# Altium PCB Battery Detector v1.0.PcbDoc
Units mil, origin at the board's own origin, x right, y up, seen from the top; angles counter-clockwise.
Board outline 2952.75 x 1181.14 mil, 2 copper layers (Top, Bottom); 48 components, 18 nets, 99 pads, 72 vias.
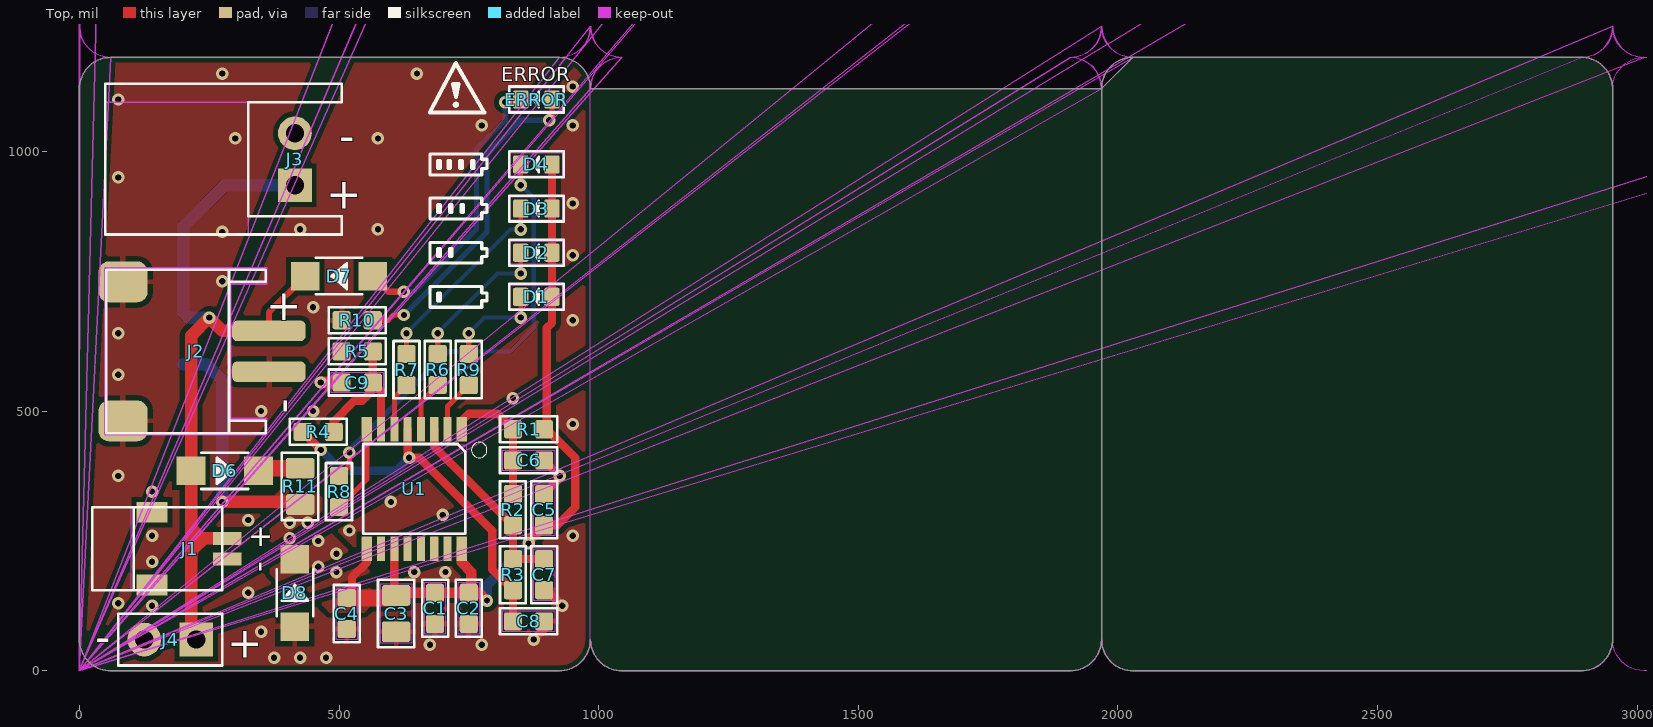
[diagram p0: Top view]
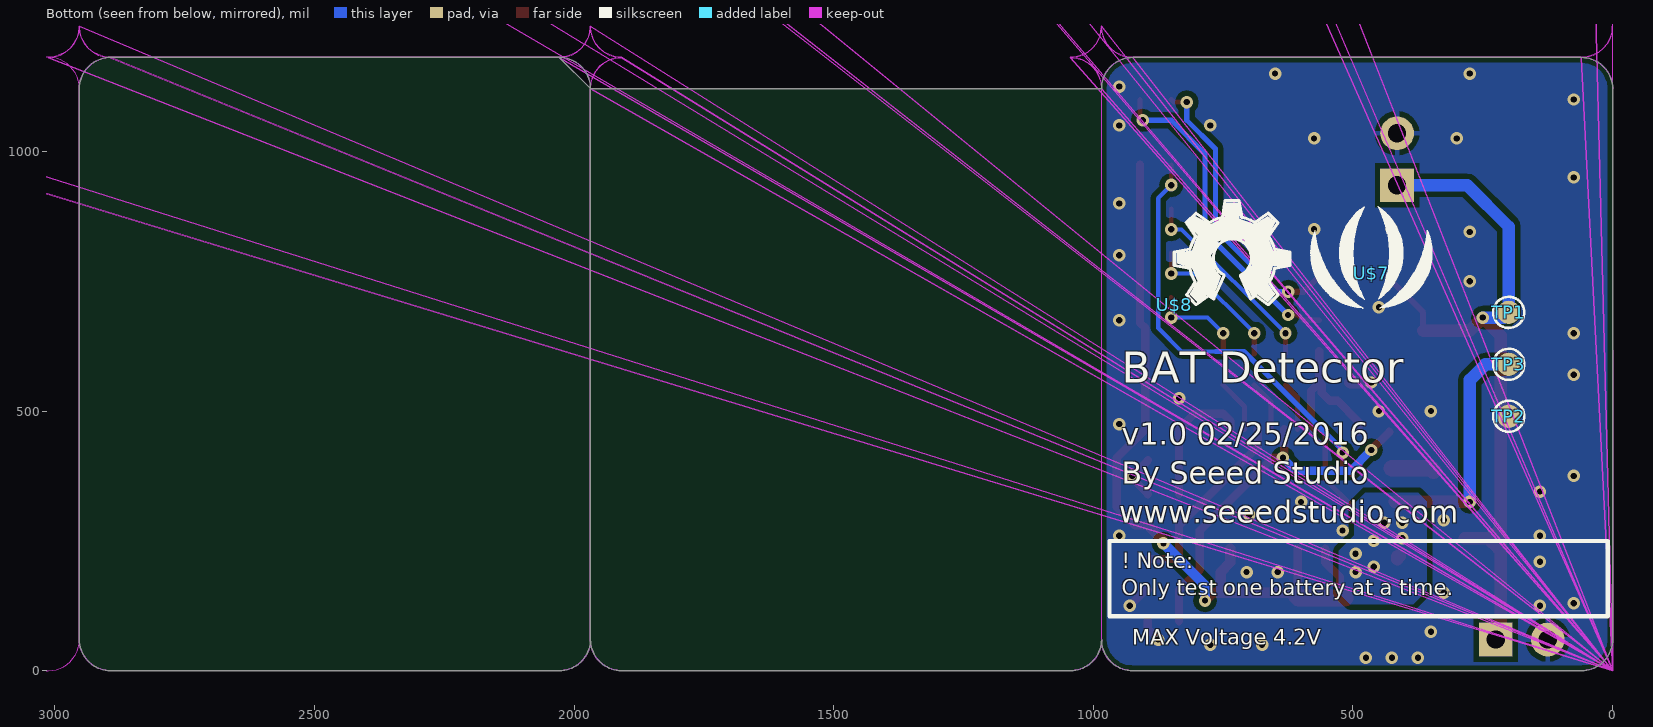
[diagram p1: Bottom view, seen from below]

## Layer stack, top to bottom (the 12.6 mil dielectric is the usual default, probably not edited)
Top Solder: solder mask 0.4, Solder Resist, Dk 3.5
Top: signal copper 1.378
Dielectric 1: dielectric 12.6, FR-4, Dk 4.8
Bottom: signal copper 1.378
Bottom Solder: solder mask 0.4, Solder Resist, Dk 3.5

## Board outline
1968.5,1121.14 cw(c2028.5,1121.14) 2028.5,1181.14 2892.75,1181.14 cw(c2892.75,1121.14) 2952.75,1121.14 2952.75,60.04 cw(c2892.75,60.04) 2892.75,0.04 2028.5,0.04 cw(c2028.5,60.04) 1968.5,60.04 1968.5,1121.14 1968.5,60 cw(c1908.5,60) 1908.5,0 1044.25,0 cw(c1044.25,60) 984.25,60 cw(c924.25,60) 924.25,0 60,0 cw(c60,60) 0,60 0,1121.1 cw(c60,1121.1) 60,1181.1 924.25,1181.1 cw(c924.25,1121.1) 984.25,1121.1 1968.5,1121.14 cw(c2028.5,1121.14)
cut-out: 60.24,1180.77 0,0 60.21,1180.77
cut-out: 936.25,2361.29 947.56,2357.86 957.99,2352.29 967.12,2344.79 974.62,2335.66 980.19,2325.23 983.62,2313.92 984.78,2302.16 0,0 984.28,2302.16 983.13,2313.82 979.73,2325.04 974.2,2335.38 966.77,2344.44 957.71,2351.87 947.37,2357.4 936.15,2360.8 924.49,2361.95 0,0 924.49,2362.45
cut-out: 1044.49,1180.77 0,0 1044.08,1180.81
cut-out: 2954.35,2313.86 2953.2,2302.2 0,0 2952.7,2302.2 2953.86,2313.96 2954.52,2316.15 2955.21,2316.69
cut-out: 2028.74,1180.81 0,0 2028,1180.88
cut-out: 3937.01,1240.94 0,0 3937.03,1241.1
cut-out: 3936.37,1229.34 3932.94,1218.03 3927.37,1207.6 3919.87,1198.47 3910.74,1190.97 3900.31,1185.4 3889,1181.97 3877.24,1180.81 0,0 3877.24,1181.31 3888.9,1182.46 3900.12,1185.86 3910.46,1191.39 3919.52,1198.82 3926.95,1207.88 3932.48,1218.22 3935.88,1229.44 3937.01,1240.94 3937.53,1241.1
cut-out: 3877.24,2361.99 1980.27,1206.37 1986.46,1198.82 1995.52,1191.39 2005.86,1185.86 2017.08,1182.46 2021.41,1182.03 3937.03,2302.2 3935.88,2313.86 3932.48,2325.08 3926.95,2335.42 3919.52,2344.48 3910.46,2351.91 3900.12,2357.44 3888.9,2360.84
cut-out: 60.23,2361.95 60.24,2361.95 30.34,1189.58 37.36,1185.82 48.58,1182.42 60.24,1181.27 60.21,1180.77 48.48,1181.93 37.17,1185.36 30.33,1189.02 0,0 30.32,1189.02 26.74,1190.93 17.61,1198.43 10.11,1207.56 4.54,1217.99 1.11,1229.3 0.45,1235.98 0.45,1241.06 1.6,1229.4 5,1218.18 10.53,1207.84 17.96,1198.78 27.02,1191.35 30.33,1189.58 60.23,2361.95 48.58,2360.8 37.36,2357.4 27.02,2351.87 17.96,2344.44 10.53,2335.38 5,2325.04 1.6,2313.82 0.45,2302.16 0.24,1238.08 0.45,1235.98 0,0 -0.05,1241.06 -0.03,1240.82 -0.05,2302.16 1.11,2313.92 4.54,2325.23 10.11,2335.66 17.61,2344.79 26.74,2352.29 37.17,2357.86 48.48,2361.29 60.24,2362.45
cut-out: 3889,2361.33 3900.31,2357.9 3910.74,2352.33 3919.87,2344.83 3927.37,2335.7 3932.94,2325.27 3936.37,2313.96 3937.53,2302.2 2021.63,1182.01 2028.74,1181.31 2028,1180.88 2020.9,1181.58 0,0 2020.68,1181.6 2016.98,1181.97 2005.67,1185.4 1995.24,1190.97 1986.11,1198.47 1979.84,1206.11 0,0 1979.7,1206.28 1978.61,1207.6 1973.04,1218.03 1969.61,1229.34 1968.74,1238.13 1967.87,1229.3 1964.44,1217.99 1958.87,1207.56 1951.37,1198.43 1942.24,1190.93 1931.81,1185.36 1920.5,1181.93 1908.74,1180.77 0,0 1908.74,1181.27 1920.4,1182.42 1931.62,1185.82 1941.96,1191.35 1951.02,1198.78 1958.45,1207.84 1963.98,1218.18 1967.38,1229.4 1968.49,1240.68 1968.49,1240.72 0,0 1968.45,1241.1 1968.46,1241.02 1968.53,1241.06 1968.5,1240.82 1968.95,1241.1 1968.96,1241.02 1969.03,1241.06 1968.99,1240.68 1970.1,1229.44 1973.5,1218.22 1979.03,1207.88 1980.13,1206.54 3877.24,2362.49
cut-out: 984.74,1240.66 985.85,1229.4 989.25,1218.18 994.78,1207.84 1002.21,1198.78 1011.27,1191.35 1021.61,1185.82 1032.83,1182.42 1044.49,1181.27 1044.08,1180.81 1032.73,1181.93 1021.42,1185.36 1010.99,1190.93 1001.86,1198.43 994.36,1207.56 988.79,1217.99 985.36,1229.3 984.49,1238.11 983.62,1229.3 980.19,1217.99 974.62,1207.56 967.12,1198.43 957.99,1190.93 947.56,1185.36 938.37,1182.57 0,0 937.64,1182.35 936.25,1181.93 924.49,1180.77 0,0 924.49,1181.27 936.15,1182.42 938.19,1183.04 984.2,1241.06 984.21,1240.97 984.28,1241.06 984.24,1240.66 984.26,1240.5 984.22,1240.45 984.21,1240.34 938.91,1183.26 938.82,1183.23 938.27,1182.54 938.37,1182.57 938.91,1183.26 947.37,1185.82 957.71,1191.35 966.77,1198.78 974.2,1207.84 979.73,1218.18 983.13,1229.4 984.21,1240.34 984.26,1240.41 984.26,1240.5 984.7,1241.06 984.71,1240.97 984.78,1241.06
cut-out: 2953.24,1240.7 2954.35,1229.44 2957.75,1218.22 2963.28,1207.88 2970.71,1198.82 2979.77,1191.39 2990.11,1185.86 3001.33,1182.46 3012.99,1181.31 3011.97,1180.91 3012.99,1180.81 0,0 3011.97,1180.91 3001.23,1181.97 2989.92,1185.4 2979.49,1190.97 2970.36,1198.47 2962.86,1207.6 2957.29,1218.03 2953.86,1229.34 2952.99,1238.15 2952.12,1229.34 2948.69,1218.03 2943.12,1207.6 2935.62,1198.47 2926.49,1190.97 2916.06,1185.4 2904.75,1181.97 2892.99,1180.81 0,0 2892.99,1181.31 2904.65,1182.46 2915.87,1185.86 2926.21,1191.39 2935.27,1198.82 2942.7,1207.88 2948.23,1218.22 2951.63,1229.44 2952.74,1240.7 2952.72,1240.87 0,0 2952.7,1241.1 2952.7,1241.07 2952.78,1241.1 2952.76,1240.91 2953.2,1241.1 2953.21,1241.07 2953.28,1241.1
cut-out: 3012.26,2361.92 3012.99,2361.99 2955.21,2316.69 2955.4,2317.34 2954.72,2316.8 2954.52,2316.15 0,0 2954.72,2316.8 2957.29,2325.27 2962.86,2335.7 2970.36,2344.83 2979.49,2352.33 2989.92,2357.9 3001.23,2361.33 3012.99,2362.49
cut-out: 3012.26,2361.92 3001.33,2360.84 2990.11,2357.44 2979.77,2351.91 2970.71,2344.48 2963.28,2335.42 2957.75,2325.08 2955.4,2317.34
cut-out: 3997.28,2362.28 4861.53,2362.28 cw(c4861.53,2302.28) 4921.53,2302.28 4921.53,1241.18 cw(c4861.53,1241.18) 4861.53,1181.18 3997.28,1181.18 cw(c3997.28,1241.18) 3937.28,1241.18 3937.28,2302.28 cw(c3997.28,2302.28)
cut-out: 3997.05,1181.22 4861.3,1181.22 cw(c4861.3,1121.22) 4921.3,1121.22 4921.3,60.12 cw(c4861.3,60.12) 4861.3,0.12 3997.05,0.12 cw(c3997.05,60.12) 3937.05,60.12 3937.05,1121.22 cw(c3997.05,1121.22)
cut-out: 3012.76,1181.14 3877.01,1181.14 cw(c3877.01,1121.14) 3937.01,1121.14 3937.01,60.04 cw(c3877.01,60.04) 3877.01,0.04 3012.76,0.04 cw(c3012.76,60.04) 2952.76,60.04 2952.76,1121.14 cw(c3012.76,1121.14)
cut-out: 1043.76,1180.84 1032.59,1179.74 1021.37,1176.34 1011.03,1170.81 1001.97,1163.38 994.54,1154.32 989.01,1143.98 985.61,1132.76 984.46,1121.1 0,0 983.96,1121.1 985.12,1132.86 988.55,1144.17 994.12,1154.6 1001.62,1163.73 1010.75,1171.23 1021.18,1176.8 1032.49,1180.23 1044.25,1181.39
cut-out: 0,0 1043.76,1180.84 1044.25,1180.89
cut-out: 1920.26,1180.23 1931.57,1176.8 1942,1171.23 1951.13,1163.73 1958.63,1154.6 1964.2,1144.17 1967.63,1132.86 1968.79,1121.1 0,0 1968.29,1121.1 1967.14,1132.76 1963.74,1143.98 1958.21,1154.32 1950.78,1163.38 1941.72,1170.81 1931.38,1176.34 1920.16,1179.74 1908.5,1180.89 0,0 1908.5,1181.39
cut-out: 1044.26,2361.93 1032.83,2360.8 1021.61,2357.4 1011.27,2351.87 1002.21,2344.44 994.78,2335.38 989.25,2325.04 985.85,2313.82 984.7,2302.16 0,0 984.2,2302.16 985.36,2313.92 988.79,2325.23 994.36,2335.66 1001.86,2344.79 1010.99,2352.29 1021.42,2357.86 1032.73,2361.29 1044.49,2362.45
cut-out: 0,0 1044.26,2361.93 1044.49,2361.95
cut-out: 1920.5,2361.29 1931.81,2357.86 1942.24,2352.29 1951.37,2344.79 1958.87,2335.66 1964.44,2325.23 1967.87,2313.92 1969.03,2302.16 0,0 1968.53,2302.16 1967.38,2313.82 1963.98,2325.04 1958.45,2335.38 1951.02,2344.44 1941.96,2351.87 1931.62,2357.4 1920.4,2360.8 1908.74,2361.95 0,0 1908.74,2362.45
cut-out: 2028.27,2361.94 2017.08,2360.84 2005.86,2357.44 1995.52,2351.91 1986.46,2344.48 1979.03,2335.42 1973.5,2325.08 1970.1,2313.86 1968.95,2302.2 0,0 1968.45,2302.2 1969.61,2313.96 1973.04,2325.27 1978.61,2335.7 1986.11,2344.83 1995.24,2352.33 2005.67,2357.9 2016.98,2361.33 2028.74,2362.49
cut-out: 0,0 2028.27,2361.94 2028.74,2361.99
cut-out: 2904.75,2361.33 2916.06,2357.9 2926.49,2352.33 2935.62,2344.83 2943.12,2335.7 2948.69,2325.27 2952.12,2313.96 2953.28,2302.2 0,0 2952.78,2302.2 2951.63,2313.86 2948.23,2325.08 2942.7,2335.42 2935.27,2344.48 2926.21,2351.91 2915.87,2357.44 2904.65,2360.84 2892.99,2361.99 0,0 2892.99,2362.49
cut-out: 4850,-189.37 ccw(c4850,-150) 4889.37,-150 ccw(c4850,-150) 4850,-110.63 ccw(c4850,-150) 4810.63,-150 ccw(c4850,-150)
cut-out: 4850,2460.63 ccw(c4850,2500) 4889.37,2500 ccw(c4850,2500) 4850,2539.37 ccw(c4850,2500) 4810.63,2500 ccw(c4850,2500)
cut-out: 75,2460.63 ccw(c75,2500) 114.37,2500 ccw(c75,2500) 75,2539.37 ccw(c75,2500) 35.63,2500 ccw(c75,2500)
cut-out: 75,-189.37 ccw(c75,-150) 114.37,-150 ccw(c75,-150) 75,-110.63 ccw(c75,-150) 35.63,-150 ccw(c75,-150)

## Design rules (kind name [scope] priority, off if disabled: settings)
BoardOutlineClearance mdCopperDimension [All] p1: gap=10 ignorepadtopadclearanceinfootprint=FALSE except(0: Arc-SplitContinuation Track-SplitContinuation SMDPad-SplitContinuation THPad-SplitContinuation Via-SplitContinuation Fill-SplitContinuation Poly-SplitContinuation Region-SplitContinuation Text-SplitContinuation)
Clearance Clearance_for_PolygonClass_Isolate_10 [InPolygonClass('Isolate_10') vs IsArc Or IsTrack Or IsPad Or IsVia Or IsFill Or IsRegion Or IsText] p1: gap=10 ignorepadtopadclearanceinfootprint=FALSE
Clearance "Clearance (Same Net)" [All] p2: gap=6 ignorepadtopadclearanceinfootprint=FALSE
Clearance [All] p3: gap=6 ignorepadtopadclearanceinfootprint=FALSE
HoleSize [All] p1: absolutevalues=TRUE maxlimit=100000 minlimit=12 maxpercent=80.000 minpercent=20.000
HoleToHoleClearance mdDrill [All] p1: gap=10 allowstackedmicrovias=TRUE
MinimumSolderMaskSliver [All] p1 off: minsoldermaskwidth=10
PasteMaskExpansion Expansion_SMDPaste_OFF [InPadClass('SMDPaste_OFF')] p1: expansion=0
PasteMaskExpansion mlMinCreamFrame [All] p2: expansion=0
PolygonConnect PolygonConnect_For_PolygonThermal_ON_Width100000_Gap100000 [InPolygonClass('PolygonThermal_ON_Width100000_Gap100000') vs Not IsVia] p1: connectstyle=Relief reliefconductorwidth=10 reliefentries=4 polygonreliefangle="90 Angle" airgapwidth=10
PolygonConnect PolygonConnect_For_PolygonThermal_ON_Width50000_Gap100000 [InPolygonClass('PolygonThermal_ON_Width50000_Gap100000') vs Not IsVia] p2: connectstyle=Relief reliefconductorwidth=5 reliefentries=4 polygonreliefangle="90 Angle" airgapwidth=10
PolygonConnect PolygonConnect_For_PolygonThermal_OFF [InPolygonClass('PolygonThermal_OFF')] p3: connectstyle=Direct reliefconductorwidth=10 reliefentries=4 polygonreliefangle="90 Angle" airgapwidth=10
PolygonConnect ThermalVias [IsVia] p4: connectstyle=Direct reliefconductorwidth=10 reliefentries=4 polygonreliefangle="90 Angle" airgapwidth=10
PolygonConnect [All] p5: connectstyle=Relief reliefconductorwidth=10 reliefentries=4 polygonreliefangle="90 Angle" airgapwidth=10
RoutingVias [All] p1: holewidth=12 width=24 viastyle="Through Hole" minholewidth=12 minwidth=24 maxholewidth=100 maxwidth=100
SolderMaskExpansion Expansion_SMDSolder_OFF [InPadClass('SMDSolder_OFF')] p1: expansion=0
SolderMaskExpansion mlMinStopFrame [All] p2: expansion=2
Width [All] p1: maxlimit=10000 minlimit=5 preferedwidth=5
26 further rules are at their usual default settings.

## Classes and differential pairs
polygon class PolygonThermal_ON_Width100000_Gap100000: Polygon_1_Net_GND Polygon_2_Net_GND
polygon class PolygonThermal_ON_Width50000_Gap100000: Polygon_2_Net_VCC
polygon class PolygonThermal_OFF: Polygon_1_Net_VCC
polygon class Isolate_10: Polygon_1_Net_GND Polygon_1_Net_VCC Polygon_2_Net_GND Polygon_2_Net_VCC
pad class SMDSolder_OFF: P1-P$1 P2-P$1 P3-P$1 P4-P$1 P5-P$1 P6-P$1 P7-P$1 P8-P$1
pad class SMDPaste_OFF: P1-P$1 P2-P$1 P3-P$1 P4-P$1 P5-P$1 P6-P$1 P7-P$1 P8-P$1 TP1-T TP2-T TP3-T

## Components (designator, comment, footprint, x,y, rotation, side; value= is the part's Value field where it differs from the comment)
C1 "DNP" C0603 685,120 r180 top
C2 "100nF" C0603 750,120 r180 top
C3 "10uF" C0805 610,110 r0 top
C4 "100nF" C0603 515,110 r180 top
C5 "DNP" C0603 895,310 r0 top
C6 "DNP" C0603 865,405 r270 top
C7 "DNP" C0603 895,185 r180 top
C8 "DNP" C0603 865,95 r270 top
C9 "DNP" C0603 535,555 r90 top
D1 "Green" LED-0603 880,720 r180 top
D2 "Green" LED-0603 880,805 r180 top
D3 "Green" LED-0603 880,890 r180 top
D4 "Green" LED-0603 880,975 r180 top
D6 "B5819W" SOD-123 280,385 r0 top
D7 "B5819W" SOD-123 500,760 r180 top
D8 "MMSZ4689" SOD-123 415,150 r90 top
ERROR "RED" LED-0603 880,1100 r180 top
FR1 "" SEEEDSTUDIO-PCB-FRAME 105,-2205 r0 top
FR2 "" SEEEDSTUDIO-PCB-FRAME 235,-1840 r0 top
J1 "JST-2P-SMD'1.0" HW2-SMD-1.0-90D 275,235 r0 top
J2 "JST-2P-SMD'2.0" HW2-SMD-2.0-90D 170,615 r270 top
J3 "JST-2P-DIP'2.54/90D'" JST2-2.54-90D 325,985 r0 top
J4 "DNP" H2-2.54 175,60 r270 top
P1 "" ROUND-MARK-1.0 400,2500 r270 bottom
P2 "" ROUND-MARK-1.0 400,2500 r90 top
P3 "" ROUND-MARK-1.0 275,-150 r270 bottom
P4 "" ROUND-MARK-1.0 275,-150 r90 top
P5 "" ROUND-MARK-1.0 4650,-150 r270 bottom
P6 "" ROUND-MARK-1.0 4650,-150 r90 top
P7 "" ROUND-MARK-1.0 4650,2500 r270 bottom
P8 "" ROUND-MARK-1.0 4650,2500 r90 top
R1 "430k" R0603 865,465 r90 top
R2 "22k" R0603 835,310 r180 top
R3 "15k" R0603 835,185 r180 top
R4 "18k" R0603 460,460 r270 top
R5 "270k" R0603 535,615 r90 top
R6 "510R" R0603 690,580 r180 top
R7 "510R" R0603 630,580 r180 top
R8 "510R" R0603 500,345 r180 top
R9 "510R" R0603 750,580 r180 top
R10 "1k" R0603 535,675 r270 top
R11 "22R" R0805 425,355 r180 top
TP1 "" TP-D45MIL 200,690 r180 bottom
TP2 "" TP-D45MIL 200,490 r180 bottom
TP3 "" TP-D45MIL 200,590 r180 bottom
U1 "CN1185" TSSOP16-0.65-5X4.4MM 645,350 r180 top
U$7 "" SEEED-SILK-280*268MIL 465,765 r180 bottom
U$8 "" OSHW_FILLX200_NOTEXT 844.25,705 r180 bottom

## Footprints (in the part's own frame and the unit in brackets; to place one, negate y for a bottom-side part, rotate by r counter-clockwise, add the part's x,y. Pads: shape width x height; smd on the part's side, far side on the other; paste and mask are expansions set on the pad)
C0603 [mil] "C0603"
  rrect25% 35x35 smd: 1(0,30) 2(0,-30)
  Top keep-out region: -20,50 20,50 20,-50 -20,-50
  silkscreen extent -25,-55 25,55
C0805 [mil] "C0805"
  rrect25% 55x40 smd: 1(0,35) 2(0,-35)
  Top keep-out region: -30,57.5 30,57.5 30,-57.5 -30,-57.5
  silkscreen extent -35,-65 35,65
H2-2.54 [mil] "H2-2.54"
  rect 65x65 / inner rect 60x60 / far side rect 65x65 hole 35: 1(0,50)
  round 65 / inner round 60 / far side round 65 hole 35: 2(0,-50)
  Top keep-out region: -50,-100 -50,100 50,100 50,-100
  Top keep-out lines w0: 50,-100 50,100 -50,100 -50,-100
  silkscreen extent -50,-100 50,100
HW2-SMD-1.0-90D [mil] "HW2-SMD-1.0-90D"
  rect 60x40 smd: 3(-135,70) 4(-135,-70)
  rect 55x25 smd: +(10,20) -(10,-20)
  Top keep-out region: -175,-80 -175,80 0,80 0,-80
  silkscreen extent -250,-80 0,80
HW2-SMD-2.0-90D [mm] "HW2-SMD-2.0-90D"
  rrect50% 2x2.4 smd: 3(3.4,-2.181) 4(-3.4,-2.181)
  rrect50% 1x3.6 smd: +(-1,4.953) -(1,4.953)
  Top keep-out lines w0.127: 4.064,-3.048 -4.064,-3.048 -4.064,4.826 -3.302,4.826 -3.302,3.048 3.302,3.048 3.302,4.826 4.064,4.826 4.064,-3.048
  silkscreen extent -4,-3 4,4.8
JST2-2.54-90D [mil] "JST2-2.54-90D"
  rect 65x65 / inner rect 60x60 / far side rect 65x65 hole 35: +(90,-50)
  round 65 / inner round 60 / far side round 65 hole 35: -(90,50)
  Top keep-out region: 0,-145 0,-110 180,-110 180,-145
  Top keep-out region: -275,-145 -275,110 0,110 0,-145
  Top keep-out region: -275,110 -275,145 180,145 180,110
  silkscreen extent -275,-145 180,145
LED-0603 [mil] "LED-0603"
  rrect25% 30x35 smd: +(-30,0) -(30,0)
  Top keep-out region: -50,-22.5 -50,22.5 50,22.5 50,-22.5
  silkscreen extent -52,-25 52,25
OSHW_FILLX200_NOTEXT [mil] "OSHW_FILLX200_NOTEXT"
  silkscreen extent 0,0 223,200
R0603 [mil] "R0603"
  rrect25% 35x35 smd: 1(0,30) 2(0,-30)
  silkscreen extent -25,-55 25,55
R0805 [mil] "R0805"
  rrect25% 55x40 smd: 1(0,35) 2(0,-35)
  silkscreen extent -35,-65 35,65
ROUND-MARK-1.0 [mil] "ROUND-MARK-1.0"
  rrect100% 40x40 smd paste-20 mask-20: P$1(0,0)
  Top circle w8: c0,0 r40
SEEED-SILK-280*268MIL [mil] "SEEED-SILK-280*268MIL"
  silkscreen extent -118,-68 118,130
SEEEDSTUDIO-PCB-FRAME [mil] "SEEEDSTUDIO-PCB-FRAME"
SOD-123 [mil] "SOD-123"
  rect 55x55 smd: +(-65,0) -(65,0)
  silkscreen extent -45,-35 45,35
TP-D45MIL [mil] "TP-D45MIL"
  rrect100% 45x45 smd paste-22.5: T(0,0)
  silkscreen extent -30,-30 30,30
TSSOP16-0.65-5X4.4MM [mil] "TSSOP16-0.65-5X4.4MM"
  rect 19.69x47.24 smd: 1(-91.54,-115.16) 8(91.54,-115.16) 9(91.54,115.16) 16(-91.54,115.16)
  rect 15.75x47.24 smd: 2(-63.98,-115.16) 3(-38.39,-115.16) 4(-12.8,-115.16) 5(12.8,-115.16) 6(38.39,-115.16) 7(63.98,-115.16) 10(63.98,115.16) 11(38.39,115.16) 12(12.8,115.16) 13(-12.8,115.16) 14(-38.39,115.16) 15(-63.98,115.16)
  Top keep-out region: -100,-85 -100,85 100,85 100,-85
  silkscreen extent -140,-90 98,87

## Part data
C1 C2 C4 C5 C6 C7 C8 C9: library part C0603
C3: library part C0805
D1 D2 D3 D4 ERROR: library part LED-0603
D6 D7 D8: library part SOD-123
FR1 FR2: library part SEEEDSTUDIO-PCB-FRAME
J1: library part HW2-SMD-1.0-90D
J2: library part HW2-SMD-2.0-90D
J3: library part JST2-2.54-90D
J4: library part H2-2.54
P1 P2 P3 P4 P5 P6 P7 P8: library part ROUND-MARK-1.0
R1 R2 R3 R4 R5 R6 R7 R8 R9 R10: library part R0603
R11: library part R0805
TP1 TP2 TP3: library part TP-D45MIL
U1: library part TSSOP16-0.65-5X4.4MM
U$7: library part SEEED-SILK-280*268MIL
U$8: library part OSHW_FILLX200_NOTEXT

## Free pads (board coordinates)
  round 78.74 hole 78.74 unplated: MH1(75,-150) MH2(4850,-150) MH3(4850,2500) MH4(75,2500)

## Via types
v1: diameter 24/24 (per signal layer), hole 12, Top to Bottom, tented both sides, 68 vias
v2: diameter 25/25 (per signal layer), hole 12, Top to Bottom, tented both sides, 4 vias

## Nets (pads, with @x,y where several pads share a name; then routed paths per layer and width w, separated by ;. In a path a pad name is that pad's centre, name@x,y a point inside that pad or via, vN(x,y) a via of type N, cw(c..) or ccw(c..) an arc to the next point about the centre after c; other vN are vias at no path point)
GND: C1.1 C2.1 C3.2 C4.1 C5.1 C6.1 C7.1 C8.1 C9.1 D8.+ J1.3 J1.4 J1.- J2.3 J2.4 J2.- J3.- J4.2 R5.1 R10.2 TP2.T U1.12 U1.13 U1.14 | length 220.6
  Top w16: v1(875,60) 895,80 C8.1 ; C7.1 900,155 v1(930,125) ; C5.1 925,370 v1(925,375) C6.1
  Top w24: v1(465,555) C9.1
  other v1: 375,25 425,25 475,25 675,50 775,50 350,75 140,125 75,130 325,150 645,190 705,190 140,210 140,260 950,260 520,270 325,290 700,300 600,325 140,345 75,375 950,475 350,500 450,500 835,525 75,570 75,650 950,675 450,700 275,750 950,800 275,845 425,850 575,850 950,900 75,950 300,1025 575,1025 775,1050 950,1050 75,1100 950,1125 275,1150 650,1150
N$1: R7.1 U1.6 | length 94.5
  Top w10: U1.6 606.61,526.61 R7.1
N$2: D6.- R11.2 | length 82.1
  Top w32: D6.- 350,390 R11.2
N$3: C6.2 R1.1 R2.2 U1.1 | length 257.8
  Top w16: U1.1 736.54,481.54 750,495 805,495 R1.1 C6.2 R2.2
N$4: C7.2 R2.1 R3.2 U1.3 | length 373
  Top w16: U1.3 683.39,431.61 R2.1 R3.2 C7.2
N$5: C8.2 R3.1 R4.2 U1.5 | length 712.3
  Top w16: R4.2 v1(465,425) ; U1.5 632.2,412.8 v1(635,410) 655,410 795,270 795,195 R3.1 C8.2
  Bottom w16: v1(465,425) 505,385 610,385 v1(635,410)
N$6: R9.1 U1.2 | length 101.8
  Top w10: U1.2 708.98,508.98 R9.1
N$7: R6.1 U1.4 | length 98.2
  Top w10: U1.4 657.8,517.8 R6.1
N$8: R8.1 U1.8 | length 172.3
  Top w10: R8.1 553.46,368.46 U1.8
N$9: D6.+ D7.- J1.+ J2.+ J3.+ J4.1 TP1.T | length 1494.8
  Top w12: J2.+ 365,690 D7.-
  Top w24: 220,235 240,255 ; J4.1 215,70 215,250 ; J1.+ 240,255 ; J2.+ 275.63,654.37 v1(250,680) 215,645 D6.+ 215,275 ; 215,250 220,255 235,255 ; 215,250 215,275 ; 215,275 235,255 ; 235,255 240,255
  Bottom w24: v1(250,680) 210,680 TP1.T 200,855 280,935 J3.+
N$10: D1.- R9.2 | length 192.4
  Top w8: v2(850,680) D1.-
  Top w10: R9.2 v1(750,650)
  Bottom w8: v1(750,650) 780,680 v2(850,680)
N$11: C9.2 R4.1 R5.2 U1.7 | length 291.3
  Top w16: R4.1 490,480 530,520 545,520 560,535 560,550 C9.2 ; R5.2 C9.2 ; U1.7 581.02,538.98 C9.2
N$12: D2.- R6.2 | length 287.6
  Top w8: v2(850,765) D2.-
  Top w10: R6.2 v1(690,650)
  Bottom w8: v1(690,650) 805,765 v2(850,765)
N$14: D3.- R7.2 | length 382.8
  Top w8: v2(850,850) D3.-
  Top w10: R7.2 v1(630,650)
  Bottom w8: v1(630,650) 830,850 841.06,850 v2(850,850)
N$16: D4.- R8.2 | length 836
  Top w8: v2(850,935) D4.-
  Top w10: R8.2 520,395 v1(520,420)
  Bottom w8: 765,615 830,615 875,660 875,910 v2(850,935)
  Bottom w10: v1(520,420) 520,425 710,615 765,615
N$17: ERROR.+ R10.1 | length 629.4
  Top w10: R10.1 595,675 605,685 v1(625,685) ; v1(905,1060) 910,1065 ERROR.+
  Bottom w10: v1(625,685) 785,845 785,995 850,1060 v1(905,1060)
N$18: D7.+ ERROR.- | length 562
  Top w10: v1(820,1095) 845,1095 ERROR.-
  Top w12: D7.+ 595,730 v1(625,730)
  Bottom w10: v1(625,730) 645,730 765,850 765,1005 820,1060 v1(820,1095)
VCC: C1.2 C2.2 C3.1 C4.2 C5.2 D1.+ D2.+ D3.+ D4.+ D8.- R1.2 R11.1 TP3.T U1.9 U1.11 U1.16 | length 2003.4
  Top w16: C4.2@525,155 525,180 553.46,208.46 U1.9 ; U1.11 606.61,148.39 C3.1 ; C5.2 920,280 955,315 955,410 900,465 R1.2 900,470 900,660 910,670 D1.+ D2.+ D3.+ D4.+
  Top w20: C3.1 615,150 C1.2 C2.2 ; U1.16 736.54,208.46 755,190 755,155 C2.2 ; v1(785,135) 770,150 C2.2 ; v1(865,245) 865,250 C5.2
  Top w24: v1(275,325) R11.1@405,325 ; D8.-@410,220 D8.- D8.-@415,220 ; R11.1@410,320 R11.1@405,325 ; R11.1@420,325 R11.1@405,325
  Top w32: C4.2 605,140 C3.1
  Bottom w20: v1(785,135) 785,165 v1(865,245)
  Bottom w24: TP3.T 245,590 275,560 v1(275,325)
  other v1: 495,190 460,200 495,225 460,250 405,255 405,285 440,285
pads on no net: P1.P$1 P2.P$1 P3.P$1 P4.P$1 P5.P$1 P6.P$1 P7.P$1 P8.P$1 U1.10 U1.15

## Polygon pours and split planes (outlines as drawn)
GND on Top "Polygon_1_Net_GND" (solid, remove dead copper, pour order 3): 155,1220 1025,1220 1025,-35 -55,-35 -55,1225 155,1225
VCC on Top "Polygon_1_Net_VCC" (solid, remove dead copper, pour order 0): 386.69,348 453.31,348 460.66,340.66 468,333.31 468,300 468,283.31 523,228.31 523,208.31 523.31,208 543.31,208 563,188.31 563,126.69 548.31,112 481.69,112 431.69,162 391.69,162 367,186.69 367,328.31
GND on Bottom "Polygon_2_Net_GND" (solid, remove dead copper, pour order 2): 185,1235 1055,1235 1055,-20 -25,-20 -25,1240 185,1240
VCC on Bottom "Polygon_2_Net_VCC" (solid, remove dead copper, pour order 1): 395,342.5 476.04,342.5 497.5,321.04 497.5,261.04 527.5,231.04 527.5,148.96 506.04,127.5 383.96,127.5 357.5,153.96 357.5,326.04 373.96,342.5

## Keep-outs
Keep-Out Layer:
  the board outline again, w0

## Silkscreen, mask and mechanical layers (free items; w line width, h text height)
Top Overlay:
  circle w6: c725,1090 r3
  lines w6: 675,700 675,740 775,740 775,727.5 785,727.5 785,712.5 775,712.5 775,700 675,700 ; 675,785 675,825 775,825 775,812.5 785,812.5 785,797.5 775,797.5 775,785 675,785 ; 675,870 675,910 775,910 775,897.5 785,897.5 785,882.5 775,882.5 775,870 675,870 ; 675,955 675,995 775,995 775,985 785,985 785,967.5 775,967.5 775,955 675,955 ; 690,712.5 695,712.5 695,727.5 690,727.5 690,712.5 ; 690,797.5 695,797.5 695,812.5 690,812.5 690,797.5 ; 690,882.5 695,882.5 695,897.5 690,897.5 690,882.5 ; 690,967.5 695,967.5 695,982.5 690,982.5 690,967.5 ; 710,967.5 715,967.5 715,982.5 710,982.5 710,967.5 ; 712.5,797.5 717.5,797.5 717.5,812.5 712.5,812.5 712.5,797.5 ; 712.5,882.5 717.5,882.5 717.5,897.5 712.5,897.5 712.5,882.5 ; 732.5,967.5 737.5,967.5 737.5,982.5 732.5,982.5 732.5,967.5 ; 735,882.5 740,882.5 740,897.5 735,897.5 735,882.5 ; 755,967.5 760,967.5 760,982.5 755,982.5 755,967.5
  lines w8: 725,1105 720,1130 725,1130 ; 725,1105 730,1130 725,1130 ; 725,1105 725,1130 ; 675,1075 780,1075 725,1170 675,1075
  text "ERROR" at 812.5,1135 h27.2
  text "-" at 500.35,1000.52 h59.5
  text "+" at 475,890 h59.5
  text "+" at 360,675 h59.5
  text "-" at 420,495 h59.5 r90
  text "+" at 325,240 h42.5
  text "-" at 365,190 h42.5 r90
  text "-" at 30.35,35.52 h59.5
  text "+" at 285,25 h59.5
Bottom Overlay:
  lines w8: 9.25,105 969.25,105 969.25,250 9.25,250 9.25,105
  text "BAT Detector" at 945,555 h59.5
  text "v1.0 02/25/2016" at 945,435 h42.5
  text "By Seeed Studio" at 945,360 h42.5
  text "www.seeedstudio.com" at 950,285 h42.5
  text "! Note:" at 945,197.5 h29.75
  text "Only test one battery at a time." at 945,145 h29.75
  text "MAX Voltage 4.2V" at 925,50 h29.75
Dimension:
  lines w0: 984.25,60 ccw(c1044.25,60) 1044.25,0 1908.5,0 ccw(c1908.5,60) 1968.5,60 1968.5,1121.1 ccw(c1908.5,1121.1) 1908.5,1181.1 1044.25,1181.1 ccw(c1044.25,1121.1) 984.25,1121.1 ; 984.25,60 cw(c924.25,60) 924.25,0 60,0 cw(c60,60) 0,60 0,1121.1 cw(c60,1121.1) 60,1181.1 924.25,1181.1 cw(c924.25,1121.1) 984.25,1121.1 ; 984.25,60 984.25,1121.1 ; 984.25,60 984.25,1121.1 ; 984.49,1241.06 ccw(c1044.49,1241.06) 1044.49,1181.06 1908.74,1181.06 ccw(c1908.74,1241.06) 1968.74,1241.06 1968.74,2302.16 ccw(c1908.74,2302.16) 1908.74,2362.16 1044.49,2362.16 ccw(c1044.49,2302.16) 984.49,2302.16 ; 984.49,1241.06 cw(c924.49,1241.06) 924.49,1181.06 60.24,1181.06 cw(c60.24,1241.06) 0.24,1241.06 0.24,2302.16 cw(c60.24,2302.16) 60.24,2362.16 924.49,2362.16 cw(c924.49,2302.16) 984.49,2302.16 ; 984.49,1241.06 984.49,2302.16 ; 984.49,1241.06 984.49,2302.16 ; 2952.76,60.04 ccw(c3012.76,60.04) 3012.76,0.04 3877.01,0.04 ccw(c3877.01,60.04) 3937.01,60.04 3937.01,1121.14 ccw(c3877.01,1121.14) 3877.01,1181.14 3012.76,1181.14 ccw(c3012.76,1121.14) 2952.76,1121.14 ; 2952.75,60.04 cw(c2892.75,60.04) 2892.75,0.04 2028.5,0.04 cw(c2028.5,60.04) 1968.5,60.04 1968.5,1121.14 cw(c2028.5,1121.14) 2028.5,1181.14 2892.75,1181.14 cw(c2892.75,1121.14) 2952.75,1121.14 ; 2952.76,60.04 2952.76,1121.14 ; 2952.75,60.04 2952.75,1121.14 ; 2952.99,1241.1 ccw(c3012.99,1241.1) 3012.99,1181.1 3877.24,1181.1 ccw(c3877.24,1241.1) 3937.24,1241.1 3937.24,2302.2 ccw(c3877.24,2302.2) 3877.24,2362.2 3012.99,2362.2 ccw(c3012.99,2302.2) 2952.99,2302.2 ; 2952.99,1241.1 cw(c2892.99,1241.1) 2892.99,1181.1 2028.74,1181.1 cw(c2028.74,1241.1) 1968.74,1241.1 1968.74,2302.2 cw(c2028.74,2302.2) 2028.74,2362.2 2892.99,2362.2 cw(c2892.99,2302.2) 2952.99,2302.2 ; 2952.99,1241.1 2952.99,2302.2 ; 2952.99,1241.1 2952.99,2302.2 ; 4921.3,60.12 cw(c4861.3,60.12) 4861.3,0.12 3997.05,0.12 cw(c3997.05,60.12) 3937.05,60.12 3937.05,1121.22 cw(c3997.05,1121.22) 3997.05,1181.22 4861.3,1181.22 cw(c4861.3,1121.22) 4921.3,1121.22 ; 4921.3,60.12 4921.3,1121.22 ; 4921.3,60.12 4921.3,1121.22 ; 4921.53,1241.18 cw(c4861.53,1241.18) 4861.53,1181.18 3997.28,1181.18 cw(c3997.28,1241.18) 3937.28,1241.18 3937.28,2302.28 cw(c3997.28,2302.28) 3997.28,2362.28 4861.53,2362.28 cw(c4861.53,2302.28) 4921.53,2302.28 ; 4921.54,1241.18 4921.54,2302.28 ; 4921.53,1241.18 4921.53,2302.28
dxf:
  lines w8: 100,2.9 100,-75 0,-75 0,-325 4925,-325 4925,-75 4825,-75 4825,0 ; 100,2362.1 100,2425 0,2425 0,2675 4925,2675 4925,2425 4825,2425 4825,2365 ; 900,0 900,-75 1075,-75 1075,0 ; 900,2365 900,2425 1075,2425 1075,2365 ; 1875,0 1875,-75 2050,-75 2050,0 ; 1875,2365 1875,2425 2050,2425 2050,2365 ; 2865,0 2865,-75 3040,-75 3040,0 ; 2865,2365 2865,2425 3040,2425 3040,2365 ; 3850,0 3850,-75 4025,-75 4025,0 ; 3850,2365 3850,2425 4025,2425 4025,2365

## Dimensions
0,2675 to 75,-325 on tFinish
0,2675 to 4925,2625 on tFinish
